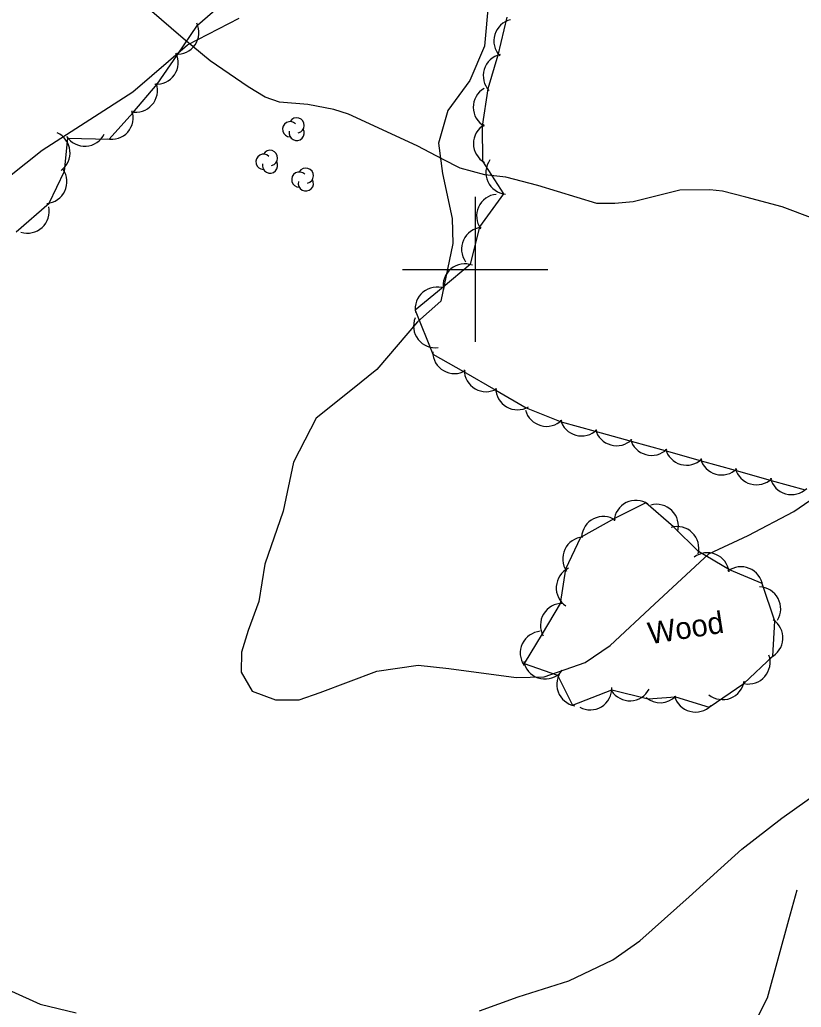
# Model space of a CAD drawing. Extents: x 643342 to 646936, y 5873857 to 5876103.
# Drawn here: x 644937.3 to 645044.9, y 5874698.4 to 5874834.4 of the extents above; entities that cross this region are included whole.
import ezdxf

# ---------------------------------------------------------------- set-up
doc = ezdxf.new("R2010")
doc.units = 0
for name, color, linetype in [('Niveau 2', 7, 'Continuous'), ('Niveau 22', 7, 'Continuous'), ('Niveau 44', 7, 'Continuous'), ('Niveau 61', 7, 'Continuous')]:
    doc.layers.add(name, color=color, linetype=linetype)

msp = doc.modelspace()

# ---------------------------------------------------------------- linework, layer by layer
at = {"layer": 'Niveau 2'}
for points in [[(645001.87, 5874836.83), (645001.28, 5874830.72), (644999.3, 5874826), (644996.27, 5874821.88), (644994.98, 5874817.39), (644995.51, 5874813.19), (644996.83, 5874807.02), (644996.95, 5874803.57), (644995.31, 5874795.6)], [(644933.58, 5874811.03), (644940.38, 5874816.4), (644952.88, 5874824.46), (644960.39, 5874830.9), (644967.52, 5874834.58)], [(644995.31, 5874795.6), (644992.07, 5874792.78), (644986.48, 5874786.22), (644983.11, 5874783.5), (644978.12, 5874779.49), (644974.98, 5874773.45), (644973.56, 5874766.69), (644971.05, 5874759.38), (644970.22, 5874754.27), (644968.78, 5874750.25), (644967.86, 5874747.27), (644967.81, 5874744.53), (644969.3, 5874741.89), (644972.52, 5874740.73), (644975.79, 5874740.7), (644978.68, 5874741.72), (644986.47, 5874744.67), (644992.16, 5874745.51), (644996.4, 5874745.01), (645005.66, 5874743.77), (645009.5, 5874743.9), (645015.17, 5874745.87), (645018.62, 5874748.18), (645024.73, 5874753.87), (645032.18, 5874760.84), (645037.63, 5874763.33), (645043.91, 5874766.65), (645049.05, 5874770.2)]]:
    msp.add_lwpolyline(points, dxfattribs=at)
at = {"layer": 'Niveau 22'}
for points in [[(645021.76, 5874809.29), (645019.23, 5874809.08), (645016.78, 5874809.08), (645008.64, 5874811.55), (645004.24, 5874812.67), (645001.37, 5874813.02), (644997.97, 5874813.92), (644995.51, 5874815.19), (644992.13, 5874816.97), (644986.64, 5874819.47), (644982.57, 5874821.39), (644980.56, 5874822.01), (644976.98, 5874822.7), (644973.08, 5874823.02), (644971.11, 5874823.69), (644968.75, 5874825.11), (644963.51, 5874828.7), (644959.83, 5874831.79), (644952.18, 5874838.39), (644947.93, 5874841.3), (644942.5, 5874844.31), (644935.38, 5874847.59)], [(645046.54, 5874806.99), (645042.29, 5874808.61), (645037.28, 5874809.96), (645034.08, 5874810.78), (645032.31, 5874810.93), (645028.19, 5874810.89), (645021.76, 5874809.29)], [(645000.63, 5874697.9), (645005.95, 5874699.8), (645012.9, 5874702.03), (645018.97, 5874704.93), (645022.7, 5874707.55), (645029.5, 5874713.59), (645036.74, 5874720.13), (645042.25, 5874724.41), (645048.9, 5874729.13)], [(644981.35, 5874675.34), (644987.4, 5874676.81), (644996.09, 5874679.76), (645003.46, 5874682.74), (645011.49, 5874684.81), (645020.42, 5874687.42), (645024.34, 5874688.99), (645030.61, 5874691.98), (645033.85, 5874693.53), (645038.93, 5874697.08), (645040.29, 5874699.66), (645043.22, 5874710.44), (645044.35, 5874714.56)], [(644936.19, 5874700.59), (644940.11, 5874698.83), (644945.06, 5874697.6)]]:
    msp.add_lwpolyline(points, dxfattribs=at)
at = {"layer": 'Niveau 44'}
for points in [[(644936.83, 5874805.15), (644941.35, 5874809.12), (644943.45, 5874813.5), (644943.94, 5874818.05), (644949.64, 5874817.92), (644952.87, 5874821.54), (644956.21, 5874825.49), (644958.96, 5874829.49), (644961.8, 5874833.61), (644965.21, 5874836.62)], [(645004.38, 5874834.71), (645003.14, 5874829.5), (645001.74, 5874824.85), (645001, 5874819.73), (645001.04, 5874814.88), (645003.9, 5874810.39), (645000.6, 5874805.86)], [(645000.6, 5874805.86), (644999.33, 5874800.66), (644995.6, 5874797.56), (644991.76, 5874794.36), (644994.19, 5874788.33), (644998.4, 5874785.91), (645002.86, 5874783.34), (645007.06, 5874780.92), (645011.86, 5874778.99), (645016.54, 5874777.7), (645021.5, 5874776.33), (645026.18, 5874775.03), (645031.13, 5874773.64), (645035.81, 5874772.33), (645040.76, 5874770.94), (645045.44, 5874769.63)], [(645023.53, 5874767.83), (645019.18, 5874765.68), (645014.52, 5874763.09), (645012.44, 5874758.7), (645011.74, 5874753.98), (645009.25, 5874749.81), (645006.78, 5874745.71), (645011.37, 5874744.13), (645013.43, 5874739.97), (645018.84, 5874742.09), (645023.82, 5874740.85), (645027.58, 5874741.15), (645032.25, 5874739.72), (645037, 5874742.97), (645041.01, 5874746.72), (645041.3, 5874751.56), (645039.53, 5874756.75), (645035.05, 5874758.61), (645030.79, 5874761.15), (645027.31, 5874764.54), (645023.53, 5874767.83)]]:
    msp.add_lwpolyline(points, dxfattribs=at)
for centre, radius, start, end in [((644958.97, 5874832.61), 3, 265.4852, 25.4631), ((644958.97, 5874832.61), 3, 265.4852, 25.4631), ((644958.97, 5874832.61), 3, 265.4852, 25.4631), ((645005.58, 5874831.45), 3, 103.211, 223.189), ((645005.58, 5874831.45), 3, 103.211, 223.189), ((645005.58, 5874831.45), 3, 103.211, 223.189), ((644956.13, 5874828.49), 3, 265.4852, 25.4631), ((644956.13, 5874828.49), 3, 265.4852, 25.4631), ((644956.13, 5874828.49), 3, 265.4852, 25.4631), ((645004.13, 5874826.66), 3, 103.211, 223.189), ((645004.13, 5874826.66), 3, 103.211, 223.189), ((645004.13, 5874826.66), 3, 103.211, 223.189), ((644953.27, 5874824.63), 3, 258.2902, 18.2681), ((644953.27, 5874824.63), 3, 258.2902, 18.2681), ((644953.27, 5874824.63), 3, 258.2902, 18.2681), ((645002.75, 5874822.32), 3, 120.3602, 240.3382), ((645002.75, 5874822.32), 3, 120.3602, 240.3382), ((645002.75, 5874822.32), 3, 120.3602, 240.3382), ((644949.94, 5874820.9), 3, 258.2902, 18.2681), ((644949.94, 5874820.9), 3, 258.2902, 18.2681), ((644949.94, 5874820.9), 3, 258.2902, 18.2681), ((644974.54, 5874819.3), 1.05, 44.1154, 269.804), ((644975.44, 5874819.83), 1.05, 282.2692, 149.7263), ((644941.24, 5874816.05), 3, 305.9206, 65.8986), ((644941.24, 5874816.05), 3, 305.9206, 65.8986), ((644941.24, 5874816.05), 3, 305.9206, 65.8986), ((644975.44, 5874818.78), 1.05, 166.9369, 29.6212), ((645002.78, 5874817.32), 3, 120.3602, 240.3382), ((645002.78, 5874817.32), 3, 120.3602, 240.3382), ((645002.78, 5874817.32), 3, 120.3602, 240.3382), ((644946.25, 5874819.96), 3, 213.6795, 333.6574), ((644946.25, 5874819.96), 3, 213.6795, 333.6574), ((644946.25, 5874819.96), 3, 213.6795, 333.6574), ((644971.77, 5874815.34), 1.05, 282.2692, 149.7263), ((644970.87, 5874814.81), 1.05, 44.1154, 269.804), ((644971.77, 5874814.29), 1.05, 166.9369, 29.6212), ((645004.49, 5874813.33), 3, 144.5687, 264.5466), ((645004.49, 5874813.33), 3, 144.5687, 264.5466), ((645004.49, 5874813.33), 3, 144.5687, 264.5466), ((644940.81, 5874812.07), 3, 274.4434, 34.4213), ((644940.81, 5874812.07), 3, 274.4434, 34.4213), ((644940.81, 5874812.07), 3, 274.4434, 34.4213), ((644975.8, 5874812.36), 1.05, 44.1154, 269.804), ((644976.7, 5874812.89), 1.05, 282.2692, 149.7263), ((644976.7, 5874811.84), 1.05, 166.9369, 29.6212), ((645003.21, 5874807.34), 3, 95.597, 215.5749), ((645003.21, 5874807.34), 3, 95.597, 215.5749), ((645003.21, 5874807.34), 3, 95.597, 215.5749), ((644938.38, 5874807.99), 3, 252.1065, 12.0844), ((644938.38, 5874807.99), 3, 252.1065, 12.0844), ((644938.38, 5874807.99), 3, 252.1065, 12.0844), ((645001.14, 5874802.79), 3, 95.597, 215.5749), ((645001.14, 5874802.79), 3, 95.597, 215.5749), ((645001.14, 5874802.79), 3, 95.597, 215.5749), ((644998.6, 5874797.75), 3, 69.7405, 189.7184), ((644998.6, 5874797.75), 3, 69.7405, 189.7184), ((644998.6, 5874797.75), 3, 69.7405, 189.7184), ((644994.75, 5874794.56), 3, 69.7405, 189.7184), ((644994.75, 5874794.56), 3, 69.7405, 189.7184), ((644994.75, 5874794.56), 3, 69.7405, 189.7184), ((644994.53, 5874792.19), 3, 157.7775, 277.7554), ((644994.53, 5874792.19), 3, 157.7775, 277.7554), ((644994.53, 5874792.19), 3, 157.7775, 277.7554), ((644997.17, 5874788.65), 3, 180.0844, 300.0623), ((644997.17, 5874788.65), 3, 180.0844, 300.0623), ((644997.17, 5874788.65), 3, 180.0844, 300.0623), ((645001.51, 5874786.15), 3, 180.0844, 300.0623), ((645001.51, 5874786.15), 3, 180.0844, 300.0623), ((645001.51, 5874786.15), 3, 180.0844, 300.0623), ((645005.84, 5874783.66), 3, 180.0844, 300.0623), ((645005.84, 5874783.66), 3, 180.0844, 300.0623), ((645005.84, 5874783.66), 3, 180.0844, 300.0623), ((645009.85, 5874781.38), 3, 194.5608, 314.5387), ((645009.85, 5874781.38), 3, 194.5608, 314.5387), ((645009.85, 5874781.38), 3, 194.5608, 314.5387), ((645014.67, 5874780.05), 3, 194.5608, 314.5387), ((645014.67, 5874780.05), 3, 194.5608, 314.5387), ((645014.67, 5874780.05), 3, 194.5608, 314.5387), ((645019.49, 5874778.71), 3, 194.5608, 314.5387), ((645019.49, 5874778.71), 3, 194.5608, 314.5387), ((645019.49, 5874778.71), 3, 194.5608, 314.5387), ((645024.31, 5874777.38), 3, 194.5608, 314.5387), ((645024.31, 5874777.38), 3, 194.5608, 314.5387), ((645024.31, 5874777.38), 3, 194.5608, 314.5387), ((645029.13, 5874776.03), 3, 194.3604, 314.3384), ((645029.13, 5874776.03), 3, 194.3604, 314.3384), ((645029.13, 5874776.03), 3, 194.3604, 314.3384), ((645033.95, 5874774.68), 3, 194.3604, 314.3384), ((645033.95, 5874774.68), 3, 194.3604, 314.3384), ((645033.95, 5874774.68), 3, 194.3604, 314.3384), ((645038.76, 5874773.33), 3, 194.3604, 314.3384), ((645038.76, 5874773.33), 3, 194.3604, 314.3384), ((645038.76, 5874773.33), 3, 194.3604, 314.3384), ((645043.57, 5874771.98), 3, 194.3604, 314.3384), ((645043.57, 5874771.98), 3, 194.3604, 314.3384), ((645043.57, 5874771.98), 3, 194.3604, 314.3384), ((645022.14, 5874765.18), 3, 56.3493, 176.3273), ((645022.14, 5874765.18), 3, 56.3493, 176.3273), ((645022.14, 5874765.18), 3, 56.3493, 176.3273), ((645025, 5874764.64), 3, 345.4289, 105.4068), ((645025, 5874764.64), 3, 345.4289, 105.4068), ((645025, 5874764.64), 3, 345.4289, 105.4068), ((645017.66, 5874762.96), 3, 56.3493, 176.3273), ((645017.66, 5874762.96), 3, 56.3493, 176.3273), ((645017.66, 5874762.96), 3, 56.3493, 176.3273), ((645027.82, 5874761.58), 3, 345.691, 105.6689), ((645027.82, 5874761.58), 3, 345.691, 105.6689), ((645027.82, 5874761.58), 3, 345.691, 105.6689), ((645015.07, 5874760.14), 3, 94.6182, 214.5961), ((645015.07, 5874760.14), 3, 94.6182, 214.5961), ((645015.07, 5874760.14), 3, 94.6182, 214.5961), ((645032, 5874757.97), 3, 7.4828, 127.4607), ((645032, 5874757.97), 3, 7.4828, 127.4607), ((645032, 5874757.97), 3, 7.4828, 127.4607), ((645036.62, 5874756.05), 3, 7.4828, 127.4607), ((645036.62, 5874756.05), 3, 7.4828, 127.4607), ((645036.62, 5874756.05), 3, 7.4828, 127.4607), ((645014.18, 5874756.14), 3, 116.2103, 236.1882), ((645014.18, 5874756.14), 3, 116.2103, 236.1882), ((645014.18, 5874756.14), 3, 116.2103, 236.1882), ((645039.09, 5874753.26), 3, 328.3763, 88.3543), ((645039.09, 5874753.26), 3, 328.3763, 88.3543), ((645039.09, 5874753.26), 3, 328.3763, 88.3543), ((645012.01, 5874750.99), 3, 89.1726, 209.1505), ((645012.01, 5874750.99), 3, 89.1726, 209.1505), ((645012.01, 5874750.99), 3, 89.1726, 209.1505), ((645039.39, 5874749.25), 3, 296.5808, 56.5588), ((645039.39, 5874749.25), 3, 296.5808, 56.5588), ((645039.39, 5874749.25), 3, 296.5808, 56.5588), ((645009.22, 5874747.16), 3, 94.6424, 214.6204), ((645009.22, 5874747.16), 3, 94.6424, 214.6204), ((645009.22, 5874747.16), 3, 94.6424, 214.6204), ((645037.63, 5874745.89), 3, 259.0148, 18.9927), ((645037.63, 5874745.89), 3, 259.0148, 18.9927), ((645037.63, 5874745.89), 3, 259.0148, 18.9927), ((645009.64, 5874746.59), 3, 191.0426, 311.0206), ((645009.64, 5874746.59), 3, 191.0426, 311.0206), ((645009.64, 5874746.59), 3, 191.0426, 311.0206), ((645014.25, 5874742.86), 3, 140.1483, 260.1262), ((645014.25, 5874742.86), 3, 140.1483, 260.1262), ((645014.25, 5874742.86), 3, 140.1483, 260.1262), ((645034.1, 5874743.75), 3, 230.9467, 350.9246), ((645034.1, 5874743.75), 3, 230.9467, 350.9246), ((645034.1, 5874743.75), 3, 230.9467, 350.9246), ((645015.85, 5874742.33), 3, 241.466, 1.4439), ((645015.85, 5874742.33), 3, 241.466, 1.4439), ((645015.85, 5874742.33), 3, 241.466, 1.4439), ((645021.31, 5874743.59), 3, 212.558, 332.5359), ((645021.31, 5874743.59), 3, 212.558, 332.5359), ((645021.31, 5874743.59), 3, 212.558, 332.5359), ((645025.51, 5874743.32), 3, 229.5464, 315.2088), ((645025.51, 5874743.32), 3, 229.5464, 315.2088), ((645025.51, 5874743.32), 3, 229.5464, 315.2088), ((645030.35, 5874742.04), 3, 195.2309, 315.2088), ((645030.35, 5874742.04), 3, 195.2309, 315.2088), ((645030.35, 5874742.04), 3, 195.2309, 315.2088)]:
    msp.add_arc(centre, radius, start, end, dxfattribs=at)
at = {"layer": 'Niveau 61'}
for points in [[(645000, 5874810), (645000, 5874800), (645000, 5874790)], [(644990, 5874800), (645000, 5874800), (645010, 5874800)]]:
    msp.add_lwpolyline(points, dxfattribs=at)

# ---------------------------------------------------------------- texts
at = {"layer": 'Niveau 44'}
msp.add_text('Wood', height=3, rotation=8.9405, dxfattribs=at).set_placement((645024.06, 5874748.36))

doc.saveas('drawing.dxf')
